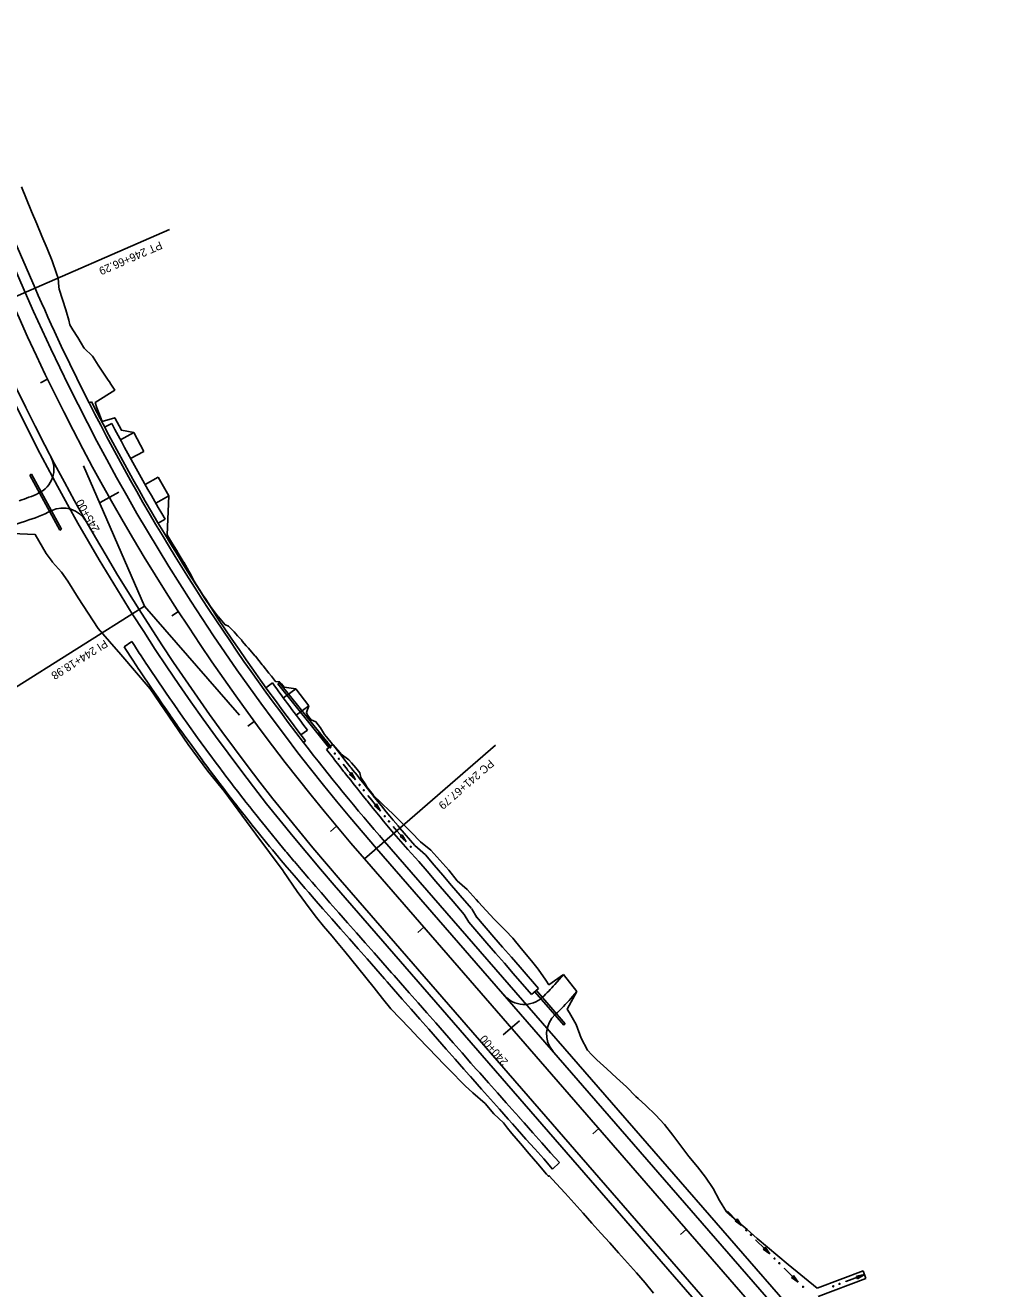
# Model space of a CAD drawing. Extents: x 948761 to 996004, y 1858548 to 1925175.
# Drawn here: x 965253 to 965972, y 1898447 to 1899394 of the extents above; entities that cross this region are included whole.
import ezdxf

# ---------------------------------------------------------------- set-up
doc = ezdxf.new("R2010")
doc.units = 0
for name, color, linetype in [('62', 7, 'Continuous'), ('R_Drainage', 7, 'Continuous'), ('R_Horz Alg', 7, 'Continuous'), ('R_Horz Alg Annot', 7, 'Continuous'), ('R_Proposed Const Limits', 7, 'Continuous'), ('R_Proposed Road', 7, 'Continuous')]:
    doc.layers.add(name, color=color, linetype=linetype)

msp = doc.modelspace()

# ---------------------------------------------------------------- linework, layer by layer
at = {"layer": '62'}
for p, q in [((965257.64, 1899057.16), (965256.32, 1899056.44)), ((965256.32, 1899056.44), (965278.88, 1899015.21)), ((965257.64, 1899057.16), (965280.2, 1899015.93)), ((965280.2, 1899015.93), (965278.88, 1899015.21)), ((965327.02, 1898927.9), (965332.9, 1898931.7)), ((965391.16, 1898847.33), (965382.14, 1898859.69)), ((965385.51, 1898843.2), (965376.49, 1898855.56)), ((965479.09, 1898857.18), (965477.42, 1898855.88)), ((965477.42, 1898855.88), (965481.92, 1898851.78)), ((965478.78, 1898850.94), (965483.5, 1898854.63)), ((965481.92, 1898851.78), (965479.09, 1898857.18)), ((965497.58, 1898833.52), (965495.92, 1898832.2)), ((965495.92, 1898832.2), (965500.49, 1898828.17)), ((965500.49, 1898828.17), (965497.58, 1898833.52)), ((965516.28, 1898810.02), (965514.63, 1898808.69)), ((965514.63, 1898808.69), (965519.23, 1898804.7)), ((965519.23, 1898804.7), (965516.28, 1898810.02)), ((965535.48, 1898786.97), (965533.88, 1898785.59)), ((965533.88, 1898785.59), (965538.59, 1898781.73)), ((965538.59, 1898781.73), (965535.48, 1898786.97)), ((965582.01, 1898727.17), (965585.38, 1898721.38)), ((965587.63, 1898731.31), (965591.4, 1898724.96)), ((965585.38, 1898721.38), (965598.93, 1898705.71)), ((965591.09, 1898725.39), (965604.21, 1898710.3)), ((965618.61, 1898683.07), (965632.48, 1898667.11)), ((965623.89, 1898687.66), (965637.76, 1898671.71)), ((965632.48, 1898667.11), (965637.76, 1898671.71)), ((965653.35, 1898541.17), (965648.23, 1898536.41)), ((965786.45, 1898499.14), (965784.93, 1898497.66)), ((965789.88, 1898494.1), (965786.45, 1898499.14)), ((965784.93, 1898497.66), (965789.88, 1898494.1)), ((965807.48, 1898477.72), (965805.99, 1898476.21)), ((965805.99, 1898476.21), (965810.99, 1898472.74)), ((965810.99, 1898472.74), (965807.48, 1898477.72)), ((965828.81, 1898456.57), (965827.32, 1898455.07)), ((965827.32, 1898455.07), (965832.33, 1898451.6)), ((965832.33, 1898451.6), (965828.81, 1898456.57)), ((965881.97, 1898457.25), (965875.98, 1898456.12)), ((965875.98, 1898456.12), (965876.73, 1898454.14)), ((965876.73, 1898454.14), (965881.97, 1898457.25))]:
    msp.add_line(p, q, dxfattribs=at)
for points in [[(965376.48, 1898855.58), (965373.4, 1898859.84), (965371.57, 1898862.41), (965367.43, 1898868.22), (965366.69, 1898869.27), (965361.85, 1898876.14), (965361.5, 1898876.65), (965357.04, 1898883.05), (965355.62, 1898885.1), (965352.27, 1898889.98), (965349.8, 1898893.59), (965347.53, 1898896.93), (965344.03, 1898902.11), (965342.82, 1898903.91), (965338.31, 1898910.67), (965338.15, 1898910.91), (965333.52, 1898917.92), (965332.63, 1898919.28), (965328.92, 1898924.97), (965327.02, 1898927.9)], [(965382.16, 1898859.67), (965379.09, 1898863.93), (965377.26, 1898866.48), (965373.13, 1898872.28), (965372.41, 1898873.3), (965367.58, 1898880.16), (965367.23, 1898880.65), (965362.79, 1898887.04), (965361.38, 1898889.08), (965358.04, 1898893.93), (965355.58, 1898897.53), (965353.32, 1898900.86), (965349.83, 1898906.03), (965348.64, 1898907.8), (965344.13, 1898914.55), (965343.99, 1898914.77), (965339.37, 1898921.77), (965338.49, 1898923.11), (965334.79, 1898928.79), (965332.9, 1898931.7)], [(965472.8, 1898863.69), (965473.98, 1898862.13), (965475.17, 1898860.56), (965476.47, 1898858.84), (965476.47, 1898858.84), (965476.54, 1898858.76), (965480.84, 1898853.17), (965481.13, 1898852.8), (965481.42, 1898852.42), (965481.92, 1898851.78)], [(965539.6, 1898775.98), (965529.25, 1898787.98), (965527.82, 1898789.63), (965524.02, 1898794.12), (965521.49, 1898797.19), (965518.92, 1898800.34), (965515.29, 1898804.8), (965513.86, 1898806.57), (965509.12, 1898812.45), (965509.07, 1898812.52), (965508.83, 1898812.81), (965506.58, 1898815.63), (965503.82, 1898819.08), (965503, 1898820.12), (965502.27, 1898821.03), (965498.84, 1898825.38), (965496.93, 1898827.82), (965493.88, 1898831.64), (965492.52, 1898833.36), (965491.88, 1898834.16), (965490.83, 1898835.49), (965488.91, 1898837.93), (965484.76, 1898843.21), (965483.95, 1898844.25), (965478.78, 1898850.94)], [(965544.95, 1898778.96), (965533.79, 1898791.9), (965532.38, 1898793.53), (965528.63, 1898797.96), (965526.13, 1898801), (965523.57, 1898804.13), (965519.94, 1898808.58), (965518.52, 1898810.33), (965513.81, 1898816.19), (965513.76, 1898816.26), (965513.51, 1898816.57), (965511.26, 1898819.37), (965508.52, 1898822.82), (965507.7, 1898823.85), (965506.98, 1898824.76), (965503.56, 1898829.08), (965501.64, 1898831.54), (965498.58, 1898835.38), (965497.22, 1898837.09), (965496.59, 1898837.89), (965495.54, 1898839.21), (965493.62, 1898841.64), (965489.5, 1898846.89), (965488.7, 1898847.92), (965483.5, 1898854.63)], [(965648.23, 1898536.41), (965641.53, 1898543.94), (965634.89, 1898551.41), (965628.24, 1898558.89), (965621.6, 1898566.36), (965618.18, 1898570.2), (965618.16, 1898570.23), (965614.96, 1898573.84), (965608.31, 1898581.31), (965601.67, 1898588.78), (965595.02, 1898596.26), (965588.38, 1898603.73), (965586.69, 1898605.63), (965585.72, 1898606.74), (965581.75, 1898611.25), (965575.15, 1898618.76), (965568.55, 1898626.27), (965561.95, 1898633.78), (965555.34, 1898641.29), (965548.74, 1898648.8), (965542.14, 1898656.31), (965535.54, 1898663.83), (965528.93, 1898671.34), (965524.13, 1898676.8), (965522.33, 1898678.85), (965515.73, 1898686.36), (965509.13, 1898693.87), (965502.52, 1898701.38), (965495.92, 1898708.89), (965489.32, 1898716.4), (965482.72, 1898723.91), (965476.11, 1898731.42), (965470.97, 1898737.28), (965469.47, 1898738.98), (965465.43, 1898743.61), (965462.71, 1898746.75), (965459.93, 1898749.97), (965456, 1898754.55), (965454.45, 1898756.36), (965449.33, 1898762.39), (965449.01, 1898762.77), (965443.6, 1898769.21), (965442.71, 1898770.28), (965438.22, 1898775.68), (965436.14, 1898778.21), (965432.88, 1898782.18), (965429.62, 1898786.17), (965427.56, 1898788.71), (965423.15, 1898794.17), (965422.28, 1898795.26), (965417.04, 1898801.83), (965416.72, 1898802.23), (965411.82, 1898808.43), (965411.74, 1898808.53), (965410.34, 1898810.33), (965406.66, 1898815.1), (965404.06, 1898818.49), (965401.54, 1898821.79), (965397.83, 1898826.68), (965396.46, 1898828.5), (965391.65, 1898834.91), (965391.42, 1898835.22), (965389.8, 1898837.4), (965386.41, 1898841.98), (965385.52, 1898843.19)], [(965653.35, 1898541.17), (965646.76, 1898548.59), (965640.12, 1898556.06), (965633.48, 1898563.54), (965626.83, 1898571.01), (965623.39, 1898574.88), (965623.37, 1898574.91), (965620.19, 1898578.49), (965613.54, 1898585.96), (965606.9, 1898593.44), (965600.25, 1898600.91), (965593.61, 1898608.38), (965591.94, 1898610.27), (965590.97, 1898611.37), (965587.01, 1898615.87), (965580.41, 1898623.38), (965573.81, 1898630.89), (965567.2, 1898638.4), (965560.6, 1898645.91), (965554, 1898653.43), (965547.4, 1898660.94), (965540.79, 1898668.45), (965534.19, 1898675.96), (965529.39, 1898681.42), (965527.59, 1898683.47), (965520.99, 1898690.98), (965514.38, 1898698.49), (965507.78, 1898706), (965501.18, 1898713.51), (965494.58, 1898721.02), (965487.97, 1898728.53), (965481.37, 1898736.04), (965476.23, 1898741.89), (965474.74, 1898743.6), (965470.71, 1898748.2), (965468, 1898751.33), (965465.23, 1898754.54), (965461.31, 1898759.1), (965459.78, 1898760.89), (965454.67, 1898766.91), (965454.36, 1898767.28), (965448.97, 1898773.7), (965448.09, 1898774.76), (965443.61, 1898780.15), (965441.54, 1898782.65), (965438.29, 1898786.61), (965435.05, 1898790.59), (965433, 1898793.11), (965428.6, 1898798.56), (965427.74, 1898799.63), (965422.51, 1898806.19), (965422.21, 1898806.57), (965417.32, 1898812.76), (965417.26, 1898812.83), (965415.88, 1898814.62), (965412.21, 1898819.37), (965409.62, 1898822.74), (965407.11, 1898826.02), (965403.41, 1898830.91), (965402.06, 1898832.7), (965397.25, 1898839.11), (965397.03, 1898839.41), (965395.42, 1898841.57), (965392.04, 1898846.14), (965391.15, 1898847.34)], [(965491.14, 1898839.95), (965491.16, 1898839.92)], [(965491.16, 1898839.92), (965491.26, 1898839.79), (965493.19, 1898837.35), (965494.24, 1898836.02), (965494.87, 1898835.23), (965496.23, 1898833.51), (965499.28, 1898829.68), (965500.47, 1898828.16)], [(965509.8, 1898816.41), (965509.82, 1898816.38)], [(965509.82, 1898816.38), (965511.17, 1898814.69), (965511.41, 1898814.39), (965511.46, 1898814.32), (965516.19, 1898808.45), (965517.62, 1898806.69), (965519.24, 1898804.7)], [(965528.79, 1898793.13), (965528.81, 1898793.11)], [(965528.81, 1898793.11), (965530.1, 1898791.58), (965531.52, 1898789.94), (965536.61, 1898784.04), (965538.59, 1898781.73)], [(965537.73, 1898782.75), (965537.75, 1898782.72)], [(965539.6, 1898775.98), (965547.9, 1898767.02), (965554.21, 1898759.63), (965560.72, 1898752.04), (965567.22, 1898744.44), (965573.73, 1898736.84), (965582.01, 1898727.17)], [(965544.95, 1898778.96), (965552.9, 1898771.94), (965559.53, 1898764.19), (965566.04, 1898756.59), (965572.54, 1898748.99), (965579.04, 1898741.4), (965587.33, 1898731.73)], [(965604.21, 1898710.3), (965610.77, 1898702.75), (965617.33, 1898695.21), (965623.89, 1898687.66)], [(965598.93, 1898705.71), (965605.49, 1898698.16), (965612.05, 1898690.61), (965618.61, 1898683.07)], [(965779.41, 1898504.84), (965786.4, 1898497.67), (965789.88, 1898494.1)], [(965800.35, 1898483.36), (965800.37, 1898483.34)], [(965800.37, 1898483.34), (965800.38, 1898483.33), (965807.47, 1898476.24), (965810.99, 1898472.74)], [(965821.65, 1898462.18), (965821.68, 1898462.16)], [(965821.68, 1898462.16), (965821.71, 1898462.12), (965828.83, 1898455.06), (965832.33, 1898451.6)], [(965867.93, 1898451.96), (965868.02, 1898451.99), (965877.41, 1898455.53), (965881.97, 1898457.25)]]:
    msp.add_lwpolyline(points, dxfattribs=at)
for centre in [(965485.01, 1898847.84), (965488.09, 1898843.89), (965503.6, 1898824.25), (965506.72, 1898820.33), (965522.43, 1898800.85), (965525.61, 1898796.97), (965541.89, 1898777.96), (965793.4, 1898490.54), (965796.89, 1898486.96), (965814.58, 1898469.24), (965818.13, 1898465.72), (965835.91, 1898448.1), (965858.53, 1898448.46), (965863.22, 1898450.23)]:
    msp.add_circle(centre, 0.375, dxfattribs=at)
at = {"layer": 'R_Drainage'}
for p, q in [((965443.53, 1898900.91), (965442.36, 1898899.97)), ((965442.36, 1898899.97), (965480.55, 1898852.32)), ((965481.72, 1898853.26), (965443.53, 1898900.91)), ((965481.72, 1898853.26), (965480.55, 1898852.32)), ((965636.06, 1898670.23), (965634.93, 1898669.25)), ((965657.75, 1898645.28), (965636.06, 1898670.23)), ((965634.93, 1898669.25), (965656.62, 1898644.3)), ((965656.62, 1898644.3), (965657.75, 1898645.28))]:
    msp.add_line(p, q, dxfattribs=at)
at = {"layer": 'R_Horz Alg'}
msp.add_line((965956.99, 1898251.42), (965507.2, 1898768.8), dxfattribs=at)
msp.add_arc((966742.64, 1899842.83), 1637.02, 203.55488, 221.00215, dxfattribs=at)
at = {"layer": 'R_Horz Alg Annot'}
for q in [(965296.58, 1899063.47), (965413.45, 1898876.65)]:
    msp.add_line((965342.4, 1898958.37), q, dxfattribs=at)
for points in [[(965242.02, 1899188.63), (965361.19, 1899240.58)], [(965264.33, 1899125.8), (965269.73, 1899128.42)], [(965309.12, 1899035.91), (965323.06, 1899043.76)], [(965342.4, 1898958.37), (965240.95, 1898894.29)], [(965362.74, 1898950.99), (965367.77, 1898954.24)], [(965419.76, 1898868.41), (965424.59, 1898871.97)], [(965507.2, 1898768.8), (965605.31, 1898854.09)], [(965481.71, 1898789.47), (965486.31, 1898793.31)], [(965547.15, 1898713.7), (965551.68, 1898717.64)], [(965611.25, 1898636.92), (965623.33, 1898647.42)], [(965678.37, 1898562.77), (965682.9, 1898566.7)], [(965743.98, 1898487.3), (965748.51, 1898491.23)]]:
    msp.add_lwpolyline(points, dxfattribs=at)
at = {"layer": 'R_Proposed Const Limits'}
for p, q in [((965880.91, 1898460.05), (965846.5, 1898447.1)), ((965883.02, 1898454.44), (965847.23, 1898440.96)), ((965880.91, 1898460.05), (965883.02, 1898454.44))]:
    msp.add_line(p, q, dxfattribs=at)
for points in [[(965280.92, 1899188.21), (965278.52, 1899195.82), (965278.22, 1899197.71), (965277.6, 1899204.14), (965276.46, 1899207.7), (965273.17, 1899217.17), (965269.41, 1899226.44), (965265.51, 1899235.65), (965261.68, 1899244.89), (965257.78, 1899254.1), (965253.97, 1899263.35), (965250.22, 1899272.62)], [(965297.16, 1899151.6), (965296.7, 1899152.38), (965294.91, 1899155.46), (965292.39, 1899159.69), (965288.78, 1899165.35), (965286.44, 1899169.2), (965285.56, 1899172.68), (965283.86, 1899178.8), (965283.3, 1899180.44), (965280.94, 1899188.16), (965280.92, 1899188.21)], [(965334.34, 1899088.4), (965325.07, 1899090.18), (965320.08, 1899099.58), (965310.7, 1899096.79), (965308.05, 1899103.23), (965306.74, 1899107.09), (965305.43, 1899110.94), (965320.05, 1899120.33), (965316.74, 1899125.53), (965316.74, 1899125.53), (965316.68, 1899125.61), (965314.73, 1899128.57), (965312.2, 1899132.29), (965309.19, 1899136.71), (965307.67, 1899138.94), (965303.85, 1899144.97), (965303.39, 1899145.74), (965297.16, 1899151.6)], [(965397.68, 1898950.41), (965391.86, 1898958.06), (965388.31, 1898963.54), (965386.45, 1898966.31), (965383.85, 1898970.25), (965381.15, 1898974.63), (965379.63, 1898977.12), (965376.33, 1898983.26), (965375.78, 1898984.22), (965375.58, 1898984.54), (965371.74, 1898991.19), (965371.39, 1898991.79), (965367.55, 1898998.08), (965366.3, 1899000.23), (965363.4, 1899004.98), (965361.17, 1899008.66), (965359.24, 1899011.88), (965360.55, 1899041.12)], [(965401.98, 1898819.51), (965389.88, 1898834.75), (965374.98, 1898854.58), (965346.69, 1898896.36), (965324.56, 1898922.14), (965307.73, 1898941.47), (965292.65, 1898964.64), (965285, 1898977.16), (965280.05, 1898983.88), (965273.36, 1898991.38), (965273.06, 1898991.8), (965268.77, 1898997.72), (965260.51, 1899011.94), (965225.63, 1899013.46)], [(965455.86, 1898896.46), (965447.11, 1898897.52), (965444.95, 1898900.09), (965443.59, 1898901.61), (965440.53, 1898901.86), (965437.45, 1898905.82), (965435.58, 1898908.18), (965431.29, 1898913.48), (965430.52, 1898914.43), (965425.53, 1898920.72), (965425.17, 1898921.18), (965420.24, 1898926.82), (965418.68, 1898928.64), (965415.65, 1898932.15), (965414.97, 1898932.95), (965412.17, 1898936.1), (965409.53, 1898938.97), (965405.42, 1898943.42), (965403.15, 1898944.37), (965402.79, 1898944.37), (965397.86, 1898950.21), (965397.68, 1898950.41)], [(965549.16, 1898781.7), (965542.22, 1898788.92), (965536.64, 1898794.39), (965535.15, 1898795.95), (965531, 1898800.06), (965528.16, 1898802.82), (965525.19, 1898805.6), (965521.06, 1898809.6), (965519.45, 1898811.2), (965514.04, 1898816.48), (965513.7, 1898816.81), (965508.81, 1898823.13), (965508.14, 1898824.28), (965504.58, 1898830), (965503.67, 1898833.26), (965500.69, 1898837.12), (965497.46, 1898840.79), (965495.41, 1898843.11), (965489.74, 1898847.42), (965488.89, 1898848.4), (965483.74, 1898854.4), (965483.07, 1898855.06), (965478.79, 1898860.29), (965478.57, 1898860.53), (965478.5, 1898860.58), (965477.19, 1898862.13), (965474.3, 1898867.14), (965470.88, 1898871.64), (965467.16, 1898873.18), (965464.45, 1898876.57), (965463.68, 1898878.72), (965465.5, 1898883.68)], [(965723.9, 1898443.33), (965717.56, 1898451.08), (965711.04, 1898458.66), (965704.41, 1898466.15), (965697.67, 1898473.54), (965690.99, 1898480.98), (965684.28, 1898488.4), (965677.58, 1898495.82), (965671.09, 1898503.43), (965664.46, 1898510.92), (965657.67, 1898518.27), (965650.92, 1898525.65), (965645.68, 1898531.41), (965645.12, 1898530.93), (965645.12, 1898530.93), (965643.6, 1898532.54), (965637.22, 1898540.24), (965630.73, 1898547.85), (965624.26, 1898555.47), (965617.77, 1898563.08), (965614.48, 1898567.06), (965614.46, 1898567.09), (965611.53, 1898570.91), (965604.28, 1898577.85), (965597.72, 1898585.4), (965588.38, 1898593.39), (965582.59, 1898598.75), (965579.8, 1898601.63), (965578.75, 1898602.66), (965574.36, 1898607.18), (965566.6, 1898615.12), (965561.58, 1898620.24), (965554.65, 1898627.46), (965547.74, 1898634.71), (965540.86, 1898641.98), (965533.97, 1898649.24), (965527.09, 1898656.51), (965520.77, 1898664.27), (965516.34, 1898670.04), (965514.57, 1898672.12), (965508.21, 1898679.84), (965501.93, 1898687.64), (965492.53, 1898699.34), (965486.15, 1898707.04), (965482.99, 1898710.92), (965476.48, 1898718.52), (965471.3, 1898725.01), (965466.64, 1898731.29), (965456.72, 1898744.45), (965446.62, 1898759.51), (965446.32, 1898759.9), (965425.93, 1898787.42), (965401.98, 1898819.51)], [(965656.31, 1898682.3), (965645.5, 1898674.58), (965643.13, 1898677.88), (965637.37, 1898686.13), (965632.31, 1898692.39), (965624.69, 1898701.6), (965618.39, 1898709.38), (965612.94, 1898715.22), (965604.43, 1898723.75), (965598.52, 1898730.14), (965592.69, 1898736.42), (965590.86, 1898738.45), (965584.17, 1898745.88), (965576.58, 1898752.54), (965570.33, 1898760.35), (965563.68, 1898767.82), (965557.04, 1898775.3), (965549.16, 1898781.7)], [(965669.53, 1898634.59), (965666, 1898644.76), (965660.82, 1898653.51), (965659.07, 1898656.11), (965666.29, 1898669.36)], [(965703.55, 1898597.9), (965696.08, 1898604.66), (965688.74, 1898611.53), (965681.3, 1898618.32), (965677.61, 1898621.95), (965677.59, 1898621.97), (965674.26, 1898625.45), (965669.53, 1898634.59)], [(965768.45, 1898521.82), (965762.87, 1898530.22), (965756.7, 1898538.1), (965750.4, 1898545.88), (965744.28, 1898553.81), (965738.22, 1898561.8), (965732.2, 1898569.81), (965725.28, 1898577.05), (965718.01, 1898583.97), (965712.32, 1898589.34), (965712.27, 1898589.3), (965712.27, 1898589.31), (965710.67, 1898590.84), (965703.55, 1898597.9)], [(965778.65, 1898504.19), (965773.27, 1898512.76), (965768.45, 1898521.82), (965768.4, 1898521.88)], [(965846.5, 1898447.1), (965824.77, 1898464.78), (965817.05, 1898471.32), (965809.29, 1898477.82), (965801.61, 1898484.39), (965793.98, 1898491.01), (965786.38, 1898497.66), (965778.65, 1898504.19)]]:
    msp.add_lwpolyline(points, dxfattribs=at)
at = {"layer": 'R_Proposed Road'}
for p, q in [((965253.02, 1899193.43), (964917.37, 1899963.34)), ((965260.35, 1899196.62), (964924.69, 1899966.58)), ((965300.9, 1899110.61), (965302.69, 1899111.51)), ((965317.78, 1899095.35), (965312.51, 1899092.49)), ((965334.34, 1899088.4), (965324.34, 1899082.98)), ((965341.92, 1899074.31), (965334.34, 1899088.4)), ((965341.92, 1899074.31), (965331.96, 1899068.91)), ((965352.62, 1899055.02), (965342.84, 1899049.41)), ((965360.55, 1899041.12), (965352.62, 1899055.02)), ((965360.55, 1899041.12), (965350.8, 1899035.53)), ((965225.63, 1899013.46), (965253.27, 1899022.1)), ((965357.88, 1899023.45), (965352.67, 1899020.47)), ((965438.22, 1898900.79), (965433.4, 1898897.21)), ((965455.86, 1898896.46), (965446.47, 1898889.48)), ((965465.5, 1898883.68), (965455.86, 1898896.46)), ((965465.5, 1898883.68), (965456.01, 1898876.63)), ((965464.47, 1898865.48), (965459.65, 1898861.9)), ((965461.49, 1898856.21), (965463.07, 1898857.44)), ((965966.03, 1898259.31), (965516.26, 1898776.67)), ((965972.06, 1898264.57), (965522.3, 1898781.92)), ((965934.35, 1898231.74), (965484.56, 1898749.12)), ((965938.9, 1898235.65), (965489.09, 1898753.05)), ((965649.78, 1898674.69), (965656.31, 1898682.3)), ((965656.31, 1898682.3), (965666.29, 1898669.36)), ((965661.91, 1898664.26), (965666.29, 1898669.36))]:
    msp.add_line(p, q, dxfattribs=at)
for centre, radius, start, end in [((966742.64, 1899842.83), 1625.02, 203.55488, 221.00215), ((966742.64, 1899842.83), 1625.02, 203.55488, 221.00215), ((966742.64, 1899842.83), 1617.02, 203.55488, 206.92488), ((966742.64, 1899842.83), 1667.02, 203.55488, 221.00215), ((966742.64, 1899842.83), 1661.02, 203.55488, 221.00215), ((966742.64, 1899842.83), 1617.02, 206.92488, 217.59988), ((966742.64, 1899842.83), 1615.02, 206.92488, 217.59988), ((966742.64, 1899842.83), 1609.02, 207.68146, 210.6133), ((965254.46, 1899061.07), 20, 294.92245, 27.7134), ((965213.58, 1899149.04), 117, 287.36365, 294.92245), ((965213.58, 1899149.04), 133, 287.36365, 296.29478), ((965281.36, 1899011.87), 20, 29.62477, 116.29478), ((966742.64, 1899842.83), 1609.02, 215.83646, 217.4033), ((966742.64, 1899842.83), 1617.02, 217.59988, 221.00215), ((965561.05, 1898750.96), 117, 312.81835, 319.32112), ((965626.98, 1898679.81), 20, 221.00215, 312.81835), ((965561.05, 1898750.96), 133, 312.15348, 319.32112), ((965663.73, 1898637.53), 20, 132.15348, 221.00215)]:
    msp.add_arc(centre, radius, start, end, dxfattribs=at)

# ---------------------------------------------------------------- texts
at = {"layer": 'R_Horz Alg'}
msp.add_text('+', height=1, rotation=131.00215, dxfattribs=at).set_placement((965507.58, 1898769.13))
msp.add_text('+', height=1, rotation=131.00215, dxfattribs=at).set_placement((965507.58, 1898769.13))
at = {"layer": 'R_Horz Alg Annot'}
for s, rotation, p in [('PT 246+66.29', 203.55488, (965354.02, 1899232)), ('245+00', 119.37488, (965309.06, 1899015.63)), ('PI 244+18.98', 212.27852, (965312.39, 1898933.5)), ('PC 241+67.79', 221.00215, (965601.05, 1898843.76)), ('240+00', 131.00215, (965615.28, 1898617.04))]:
    msp.add_text(s, height=6, rotation=rotation, dxfattribs=at).set_placement(p)

doc.saveas('drawing.dxf')
